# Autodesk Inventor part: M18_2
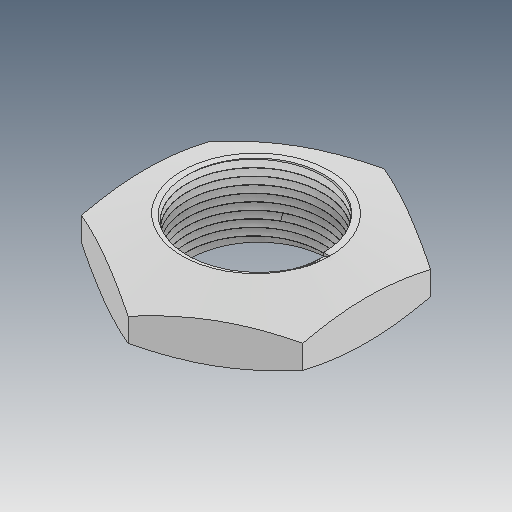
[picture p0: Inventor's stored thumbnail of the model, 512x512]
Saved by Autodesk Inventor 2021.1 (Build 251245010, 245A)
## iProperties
Created: 2019-04
Part Number: M18_2
Material: Ogólny
Document SubType Name: Modeling
Designer: user
Density: 1 g/cm^3
Appearance: Domyślna
Author: user
Revision Number: ÈÎºÎ
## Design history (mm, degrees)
feature "ÊäÈë1"
node "Bryła1"
